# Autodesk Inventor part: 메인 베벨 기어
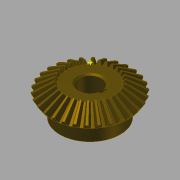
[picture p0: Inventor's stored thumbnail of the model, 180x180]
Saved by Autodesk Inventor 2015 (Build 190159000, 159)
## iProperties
Created: 2014-10
Part Number: 메인 베벨 기어
Material: 강철, 탄소
Document SubType Name: Modeling
Designer: KYOUNG IL JANG
Categories: <?xml version="1.0" encoding="UTF-16"?> <MemberInstance><Categories><FamilyTemplate><FamilyTemplateParameter ValueType="xs:double" Id="1" ObjectReferenceKey="da
Mass: 269.926 g
Surface Area: 108.837 cm^2
Volume: 34.2981 cm^3
Density: 7.87 g/cm^3
Appearance: 얼룩무늬
CustomPartVersion: 1
Author: SeoGD™ [www.esajin.kr]
Revision Number: 1
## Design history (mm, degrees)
node "맨 위 점"
node "메쉬 평면2"
sketch "톱니 본체 스케치"
  geometry: L1 (0, 0)-(28.669, -21.997); L2 (28.669, -21.997)-(31.109, -18.336); L3 (31.109, -18.336)-(0, 0); L4 (30, -20)-(0, 0); L5 (17.219, -13.212)-(18.685, -11.013); L6 (28.669, -21.997)-(17.219, -13.212); L7 (31.109, -18.336)-(18.685, -11.013); L8 (0, -39.387)-(0, 6.564) reference; L9 (0, -20)-(31.109, -20)
  constraints: 16 end point, 4 point on line, 3 perpendicular, 2 collinear, 1 horizontal alignment, 1 vertical alignment
  dimensions: "d0" = 60 diameter of L4.start L8 (= da_de); "d1" = 57.33744 diameter of L1.end L8 (= da_dfe); "d2" = 62.2188 diameter of L2.end L8 (= da_dae); "d3" = 14.4 distance between parallel lines of L2 L5 (= da_b); "d4" = 18.3359 vertical distance of L2.end L1.start (= da_ve)
revolve "톱니 본체" sketch "톱니 본체 스케치" stored, may be unused: angle "d5" = 90 deg
node "시작점"
node "톱니 평면"
sketch "시작 스케치"
  geometry: L1 (0, -23.505)-(0, 10.645) reference; L2 (-0.709, -2.928)-(0.709, -2.928); A1 r 19.188 centre (-19.457, -7.014) between (-0.709, -2.928) and (-3.232, 3.229); A2 r 19.188 centre (19.457, -7.014) between (3.232, 3.229) and (0.709, -2.928); A3 r 57.403 centre (0, -54.083) between (3.232, 3.229) and (-3.232, 3.229); 1 further point
  constraints: 6 point on circle, 3 centre point, 3 symmetric about line, 2 end point, 1 coincident, 1 perpendicular, 1 other
  dimensions: "d7" = 19.18795 radius of A1 (= fd_rr); "d8" = 19.45712 horizontal distance of point (0, -54.083) A1.centre (= fd_x); "d9" = 47.06905 vertical distance of point (0, -54.083) A1.centre (= fd_y); "d57" = 57.40327 radius of A3 (= 0.5 x fd_dva + 0.3 x da_he); "d58" = 51.15527 distance from line of A3.centre L2 (= 0.5 x fd_dva - 1.12 x da_he)
node "끝점"
  node "끝 평면"
sketch "3D 스케치 오른쪽"
  node "Helical Curve Right" dims "d65" = 229.90621 (computed from da_dm, da_delta, da_beta), "d66" = 31.5, "d67" = 60 (= da_de), "d68" = -9.82794 (= -da_delta), "d69" = 8.10972 (computed from fd_loft, da_delta)
node "끝 평면 오른쪽"
sketch "끝 스케치 오른쪽"
  geometry: L1 (0, -41.54)-(0, 13.178) reference; L2 (-0.422, -1.69)-(0.422, -1.69); A1 r 11.427 centre (-11.587, -4.123) between (-0.422, -1.69) and (-1.925, 1.977); A2 r 11.427 centre (11.587, -4.123) between (1.925, 1.977) and (0.422, -1.69); A3 r 34.184 centre (0, -32.153) between (1.925, 1.977) and (-1.925, 1.977); 1 further point
  constraints: 6 point on circle, 3 centre point, 3 symmetric about line, 2 end point, 1 coincident, 1 perpendicular, 1 other
  dimensions: "d70" = 11.58699 horizontal distance of A3.centre A1.centre (computed from fd_x, fd_ratio); "d71" = 28.03028 vertical distance of point (0, -32.153) A1.centre (computed from fd_y, fd_ratio); "d72" = 11.4267 radius of A1 (computed from fd_rr, fd_ratio); "d73" = 30.46369 distance from line of point (0, -32.153) L2 (computed from d58, fd_ratio); "d74" = 34.18446 radius of A3 (computed from d57, fd_ratio)
feature "로프트 오른쪽" sketch "끝 스케치 오른쪽" dims "d75" = 0, "d77" = 0, "d79" = 0, "d80" = 90 deg, "d85" = 20, "d92" = 90 deg, "d93" = 90 deg, "da_teethtype" = 0 [user parameter]
sketch "3D 스케치 왼쪽"
  node "Helical Curve Left" dims "d26" = 229.90621 (computed from da_dm, da_delta, da_beta), "d27" = 8.10972 (computed from fd_loft, da_delta), "d28" = 60 (= da_de), "d29" = -9.82794 (= -da_delta)
node "끝 평면 왼쪽"
sketch "끝 스케치 왼쪽" dims "d56" = 10.3728 (derived)
  geometry: L1 (0, -43.753)-(0, 15.405) reference; L2 (-0.422, -1.678)-(0.422, -1.678); A1 r 11.427 centre (-11.587, -4.111) between (-0.422, -1.678) and (-1.925, 1.988); A2 r 11.427 centre (11.587, -4.111) between (1.925, 1.988) and (0.422, -1.678); A3 r 34.184 centre (0, -32.142) between (1.925, 1.988) and (-1.925, 1.988); 2 further points; 1 other entity
  constraints: 6 point on circle, 3 centre point, 3 symmetric about line, 2 end point, 1 coincident, 2 other
  dimensions: "d30" = 11.4267 radius of A1 (computed from fd_rr, fd_ratio); "d31" = 11.58699 horizontal distance of point (0, -32.142) A1.centre (computed from fd_x, fd_ratio); "d32" = 28.03028 vertical distance of A1.centre point (0, -32.142) (computed from fd_y, fd_ratio); "d61" = 34.18446 radius of A3 (computed from d57, fd_ratio); "d62" = 30.46369 distance from line of point (0, -32.142) L2 (computed from d58, fd_ratio)
feature "로프트 왼쪽" sketch "끝 스케치 왼쪽" dims "d35" = 0, "d37" = 0, "d39" = 0, "d40" = 90 deg, "d84" = 10, "d90" = 90 deg, "d91" = 90 deg, "da_teethtype" = 0 [user parameter]
sketch "본체 스케치"
  geometry: L1 (0, -35.038)-(0, -19.531) reference; L2 (28.669, -21.997)-(17.219, -13.212) reference; L3 (17.219, -13.212)-(0, -13.212); L4 (28.669, -21.997)-(0, -21.997)
  constraints: 4 end point, 2 perpendicular, 2 point on line
revolve "본체 고정" sketch "본체 스케치" stored, may be unused: angle "d46" = 90 deg
feature "피치 지름" dims angle "d47" = 90 deg
sketch "스케치8"
  geometry: C1 r 22.5 at (0, 0); 1 further point
  constraints: 1 centre point, 1 coincident
  dimensions: "d94" = 45 diameter of C1
extrude "돌출1" join sketch "스케치8" distance "d95" = 13; taper "d96" = 0 deg
sketch "스케치9"
  geometry: 1 further point
hole "구멍1" sketch "스케치9" at (0, 0) diameter "d97" = 17; stored, may be unused: countersink angle "d101" = 90 deg, drill point angle "d103" = 118 deg; dims "d98" = 6, "d99" = 4, "d100" = 2, "d102" = 8
sketch "스케치10"
  geometry: L1 (8.124, 2.5)-(10.8, 2.5); L2 (10.8, 2.5)-(10.8, -2.5); L3 (10.8, -2.5)-(8.124, -2.5); A1 r 8.5 centre (0, 0) between (8.124, 2.5) and (8.124, -2.5) reference; 1 further point
  constraints: 6 end point, 2 parallel, 2 point on circle, 1 horizontal, 1 perpendicular
  dimensions: "d104" = 5 distance of L1.end L2.end; "d112" = 19.3 dimension on A1 L2
extrude "돌출2" cut sketch "스케치10" stored distance "d106" = 10; taper "d107" = 0 deg
chamfer "모따기1" distance "d108" = 1; stored, may be unused: second distance "d109" = 2, angle "d110" = 45 deg
fillet "모깎기1" dims "d111" = 2
body "Solid1"
feature "로프트" dims "d17" = 0, "d18" = 90 deg, "d19" = 0, "d20" = 90 deg, "d89" = 0, "da_teethtype" = 0 [user parameter]
pattern_circular "원형 패턴" dims angle "d22" = 360 deg, "d88" = 0, "da_teethtype" = 0 [user parameter]
pattern_circular "원형 패턴 오른쪽" dims angle "d82" = 360 deg, "da_teethtype" = 0 [user parameter]
pattern_circular "원형 패턴 왼쪽" dims angle "d42" = 360 deg, "da_teethtype" = 0 [user parameter]
sketch "끝 스케치"
  geometry: L1 (0, -15.359)-(0, 6.983) reference; L2 (-0.422, -1.69)-(0.422, -1.69); A1 r 11.427 centre (-11.587, -4.123) between (-0.422, -1.69) and (-1.925, 1.977); A2 r 11.427 centre (11.587, -4.123) between (1.925, 1.977) and (0.422, -1.69); A3 r 34.184 centre (0, -32.153) between (1.925, 1.977) and (-1.925, 1.977); 1 further point
  constraints: 6 point on circle, 3 centre point, 3 symmetric about line, 2 end point, 1 coincident, 1 other
  dimensions: "d12" = 11.4267 radius of A1 (computed from fd_rr, fd_ratio); "d15" = 11.58699 horizontal distance of A1.centre point (0, -32.153) (computed from fd_x, fd_ratio); "d16" = 28.03028 vertical distance of A1.centre point (0, -32.153) (computed from fd_y, fd_ratio); "d59" = 34.18446 radius of A3 (computed from d57, fd_ratio); "d60" = 30.46369 distance from line of A3.centre L2 (computed from d58, fd_ratio)
sketch "Sketch6"
  geometry: L1 (30, -20)-(0, 0) reference; L2 (0, -37.8)-(0, 6.3) reference
body "Srf1"
other parameters: "da_b" = 14.4 [user parameter; used in 2 equation terms], "da_de" = 60 [user parameter; used in 4 equation terms], "da_dae" = 62.2188 [user parameter; used in 2 equation terms], "da_dfe" = 57.33744 [user parameter; used in 1 equation term], "da_le" = 36.05551 [user parameter; used in 1 equation term], "da_omega" = 90 deg [user parameter; used in 1 equation term], "da_beta" = 0 [user parameter; used in 2 equation terms], "da_delta" = 9.82794 [user parameter; used in 8 equation terms], "da_alpha" = 20 deg [user parameter; used in 2 equation terms], "da_he" = 4.4 [user parameter; used in 4 equation terms], "da_ve" = 18.3359 [user parameter; used in 1 equation term], "fd_dv" = 108.16654 (computed from da_de, da_delta) [user parameter; used in 1 equation term], "fd_dva" = 112.16654 (computed from da_dae, da_delta) [user parameter; used in 3 equation terms], "fd_dvb" = 101.6433 (computed from fd_dv, da_alpha) [user parameter; used in 2 equation terms], "da_zv" = 540.83269 [user parameter; used in 1 equation term], "fd_loft" = 14.62 (= da_b + 0.05 x da_he) [user parameter; used in 4 equation terms], "fd_ratio" = 5.95514 (computed from da_le, fd_loft) [user parameter; used in 15 equation terms], "fd_rr" = 19.18795 (computed from fd_dd, fd_dvb) [user parameter; used in 6 equation terms], "fd_angle" = 0.29367 (computed from da_zv) [user parameter; used in 4 equation terms], "fd_x1" = 1.58802 (computed from da_dvw, fd_angle) [user parameter; used in 1 equation term], "fd_y1" = 54.05995 (computed from da_dvw, fd_angle) [user parameter; used in 1 equation term], "fd_x2" = 17.8691 (computed from fd_rr, fd_angle2, fd_angle) [user parameter; used in 1 equation term], "fd_y2" = 6.9909 (computed from fd_rr, fd_angle2, fd_angle) [user parameter; used in 1 equation term], "fd_x" = 19.45712 (= fd_x1 + fd_x2) [user parameter; used in 4 equation terms], "fd_y" = 47.06905 (= fd_y1 - fd_y2) [user parameter; used in 4 equation terms], "fd_angle2" = 3.43555 (computed from fd_dvb, fd_dd, da_alpha) [user parameter; used in 2 equation terms], "fd_dd" = 108.64654 (= fd_dva - 0.8 x da_he) [user parameter; used in 2 equation terms], "da_dvw" = 108.16654 [user parameter; used in 2 equation terms], "d11" = 14.62 (= fd_loft), "da_dm" = 48.01848 [user parameter; used in 2 equation terms], "da_x" = 0 [user parameter], "da_m" = 2 [user parameter], "d48" = 0, "d49" = 0, "d50" = 90 deg (= da_omega), "d51" = 6 deg (computed from da_z), "d52" = 0, "d53" = 0, "d54" = 0
